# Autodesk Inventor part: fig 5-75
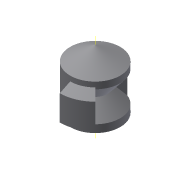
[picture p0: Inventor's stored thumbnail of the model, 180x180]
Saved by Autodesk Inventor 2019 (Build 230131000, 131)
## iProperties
Created: 2004-05
Part Number: fig 5-75
Document SubType Name: Modeling
Designer: CADCIM Technologies
Manufacturer: Standard
Standards Organization: Custom
Density: 1 g/cm^3
Material: Generic
Appearance: Default
Author: CADCIM Technologies
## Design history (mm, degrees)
sketch "Sketch1"
  geometry: L1 (0, -21.51)-(0, 21.51); L2 (0, 21.51)-(-14.639, 13.059); L3 (-14.639, 13.059)-(-14.639, -13.059); L4 (-14.639, -13.059)-(0, -21.51); 2 further points
  constraints: 8 end point, 1 coincident, 1 equal length, 1 midpoint, 1 parallel, 1 vertical, 1 other
  dimensions: "d3" = 120 deg angle of L4 L3
revolve "Revolution1" sketch "Sketch1" stored, may be unused: angle "d0" = 90 deg
workaxis "Work Axis1"
sketch "Sketch2"
  geometry: L1 (-15.658, 10.423)-(-7.144, 0); L2 (-7.144, 0)-(-15.658, -9.738); L3 (-15.658, -9.738)-(-15.658, 10.423); L4 (0, -25.812)-(0, 34.416) reference
  constraints: 6 end point, 1 vertical
revolve "Revolution2" sketch "Sketch2" stored, may be unused: angle "d4" = 140 deg
sketch "Sketch3"
  geometry: L1 (-14.955, 9.983)-(-20.736, 7.191); L2 (-20.736, 7.191)-(-20.736, -7.686); L3 (-20.736, -7.686)-(-15, -10.57); L4 (0, -25.812)-(0, 34.416) reference
  constraints: 6 end point, 1 equal length, 1 vertical
revolve "Revolution4" sketch "Sketch3" stored, may be unused: angle "d9" = 45 deg
body "Solid1"
other parameters: "d11" = 45 deg
